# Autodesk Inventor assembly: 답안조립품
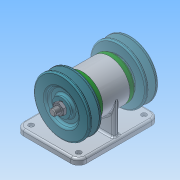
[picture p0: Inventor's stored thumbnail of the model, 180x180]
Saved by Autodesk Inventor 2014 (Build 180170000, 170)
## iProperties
Created: 2019-09
Part Number: 답안조립품
Document SubType Name: Assembly
Designer: net
Author: net
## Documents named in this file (10)
- C:\Users\net\Desktop\490904V1026\답안조립품.iam
- C:\Users\net\Desktop\490904V1026\본체.ipt
- C:\Users\net\Desktop\490904V1026\V-벨트풀리.ipt
- C:\Users\net\Desktop\490904V1026\너트 M10x1.ipt
- C:\Users\net\Desktop\490904V1026\베어링 6004.ipt
- C:\Users\net\Desktop\490904V1026\볼트 M4.ipt
- C:\Users\net\Desktop\490904V1026\오일 실 17 30 5.ipt
- C:\Users\net\Desktop\490904V1026\축.ipt
- C:\Users\net\Desktop\490904V1026\커버.ipt
- C:\Users\net\Desktop\490904V1026\키 5 x 5 x 12.ipt
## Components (2 placed, 1 different names)
1. V-벨트풀리:1
2. V-벨트풀리:2
